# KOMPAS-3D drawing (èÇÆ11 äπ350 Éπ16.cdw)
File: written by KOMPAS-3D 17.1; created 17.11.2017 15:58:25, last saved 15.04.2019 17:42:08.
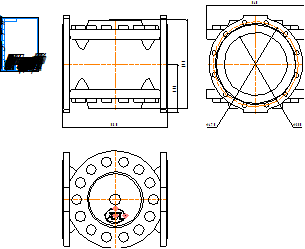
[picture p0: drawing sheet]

Sheet 1: A4, portrait

Title block, sheet 1: name: КАТ11 Ду350 Ру16; material: Внимание! Данный продукт является объектом авторского права ООО «Торговый Дом АДЛ». / Запрещается изменение, копирование, распространение / (в том числе путем копирования на другие сайты и ресурсы в Интернете) / или любое иное использование информации и объектов без предварительного / согласия правообладателя (ООО «Торговый Дом АДЛ»).; mass: 12,4; sheets: 1; organisation: ООО "Торговый дом АДЛ"; sheet format: A4; stored path: \\adlc.lan\data\АДЛ_ПКД\3D-модели\ADL production\Клапаны КАТ ГРАНРЕГ\КАТ11\KOMPAS 2D\КАТ11 Ду350 Ру16.cdw

Views: Вид 1, Проекционный вид 2, Проекционный вид 3
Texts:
  kka
  adl
Dimensions and other numbers on the sheet: 580; 270; 495; 540; 470; 350; 1:1; 1; 12,4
